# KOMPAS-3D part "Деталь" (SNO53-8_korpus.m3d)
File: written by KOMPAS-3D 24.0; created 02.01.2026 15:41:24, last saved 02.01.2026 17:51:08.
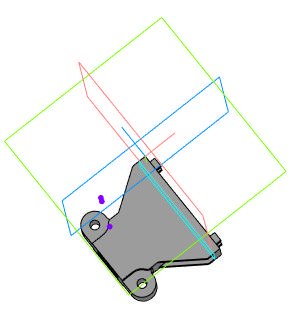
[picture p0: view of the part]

Document properties: Автор: Egor; Полное имя файла: Y:\my projects\KOMPAS\SNO53-8_korpus.m3d

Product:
- Part/product: Деталь
    Масса: 0.019218

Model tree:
1. Эскиз:1
2. Элемент выдавливания:1
     Расстояние 1 = 8.5
3. Смещенная плоскость:1  (with: Грань.Элемент выдавливания:1)
     Расстояние = 2
4. Эскиз:2
5. Элемент выдавливания:2
     Расстояние 2 = 13
6. Массив по сетке:1  (with: Элемент выдавливания:2, Смещенная плоскость:1, Эскиз:2)  (2 pattern instances)
     Наклон = 90; Шаг 1 = 23; Угол раствора = 90
7. Эскиз:3  (with: Грань.Элемент выдавливания:1, Вершина.Элемент выдавливания:1)
8. Элемент выдавливания:3
     Расстояние 2 = 1.5
9. Точка:1  (with: Вершина.Элемент выдавливания:3)
     X = -17.3377; Y = 8.5; Z = -7; Координата X = -17.3377; Координата Y = 8.5; Координата Z = -7
10. Точка:2
     X = -15; Y = 2; Z = -1; Координата X = -15; Координата Y = 2; Координата Z = -1
11. Точка:3
     X = -15; Y = 7; Z = -1; Координата X = -15; Координата Y = 7; Координата Z = -1
12. Массив по сетке:2  (with: Элемент выдавливания:3)  (2 pattern instances)
     Шаг 1 = 7; Угол раствора = 90
13. Эскиз:4  (with: Грань.Элемент выдавливания:1, Ребро.Элемент выдавливания:1)
14. Элемент выдавливания:4
     Расстояние 2 = 22.5
15. Эскиз:5  (with: Грань.Элемент выдавливания:1, Ребро.Элемент выдавливания:1)  (labels: Ребро.Элемент выдавливания:2.Экземпляр ( 2, 1 ))
16. Элемент выдавливания:5
17. Эскиз:6  (with: Грань.Элемент выдавливания:1, Ребро.Элемент выдавливания:1)
18. Элемент выдавливания:6
     Расстояние 2 = 24
19. Скругление:1  (with: Ребро.Элемент выдавливания:4)
     Радиус = 0.7
20. Эскиз:7  (with: Грань.Элемент выдавливания:1, Ребро.Элемент выдавливания:1)
21. Элемент выдавливания:7
     Расстояние 1 = 1.6
22. Скругление:2  (with: Ребро.Элемент выдавливания:6)
     Радиус = 0.1
23. Скругление:3  (with: Ребро.Элемент выдавливания:1)
     Радиус = 0.7
24. Скругление:4  (with: Ребро.Элемент выдавливания:1, Ребро.Элемент выдавливания:3)  (labels: Ребро.Элемент выдавливания:3.Экземпляр ( 2, 1 ))
     Радиус = 1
